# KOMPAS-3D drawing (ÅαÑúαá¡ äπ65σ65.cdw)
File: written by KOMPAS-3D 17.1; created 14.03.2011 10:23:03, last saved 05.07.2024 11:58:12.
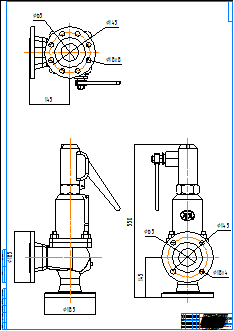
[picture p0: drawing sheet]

Sheet 1: A0, portrait

Title block, sheet 1: name: Прегран Ду65х65; material: Внимание! Данный продукт является объектом авторского права ООО «Торговый Дом АДЛ». / Запрещается изменение, копирование, распространение / (в том числе путем копирования на другие сайты и ресурсы в Интернете) / или любое иное использование информации и объектов без предварительного / согласия правообладателя (ООО «Торговый Дом АДЛ»).; scale: 1:1; sheets: 1; organisation: ООО "Торговый дом АДЛ"; sheet format: A0; stored path: C:\Users\tra\Desktop\2д чертежи\Предохранительные клапаны ПРЕГРАН\ПРЕГРАН 096\ПРЕГРАН КПП 096-03-40\KOMPAS 2D\Прегран Ду65х65.cdw

Views: Спереди 1, Проекционный вид 2, Проекционный вид 3
Dimensions and other numbers on the sheet: 145; 65; 550; 185; 18; 1:1; 1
